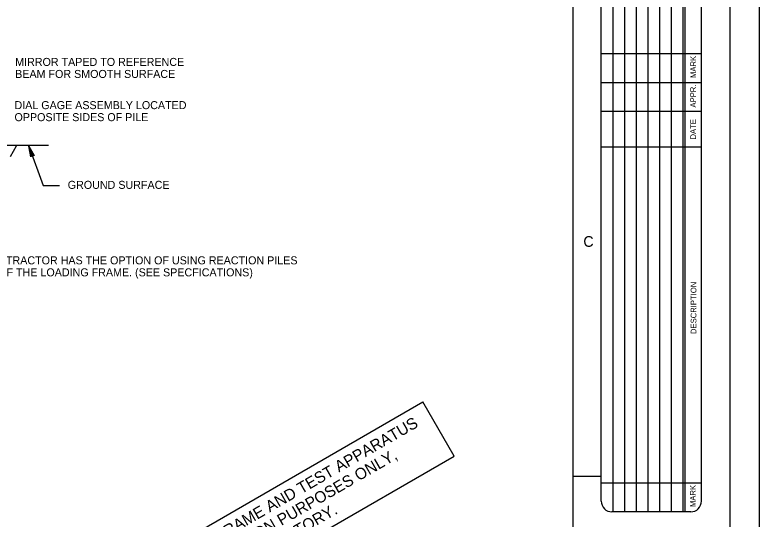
# Model space of a CAD drawing. Extents: x 22378.6 to 22422.6, y 22377.7 to 22411.7.
# Drawn here: x 22409.64 to 22422.65, y 22393.91 to 22402.72 of the extents above; entities that cross this region are included whole.
import ezdxf

# ---------------------------------------------------------------- set-up
doc = ezdxf.new("R2010")
doc.units = 0
for name, color, linetype in [('Level 1', 7, 'Continuous'), ('Level 10', 7, 'Continuous'), ('Level 2', 7, 'Continuous'), ('Level 4', 7, 'Continuous'), ('Level 7', 7, 'Continuous'), ('Level 8', 7, 'Continuous'), ('Level 9', 7, 'Continuous')]:
    doc.layers.add(name, color=color, linetype=linetype)

msp = doc.modelspace()

# ---------------------------------------------------------------- linework, layer by layer
at = {"layer": 'Level 1'}
for p, q in [((22420.089, 22409.031), (22420.089, 22394.031)), ((22420.293, 22409.031), (22420.293, 22394.031)), ((22420.497, 22409.031), (22420.497, 22394.031)), ((22420.701, 22409.031), (22420.701, 22394.031)), ((22420.905, 22409.031), (22420.905, 22394.031)), ((22421.109, 22409.031), (22421.109, 22394.031)), ((22421.313, 22409.031), (22421.313, 22394.031)), ((22421.349, 22409.031), (22421.349, 22394.031)), ((22421.637, 22401.531), (22419.885, 22401.531)), ((22409.557, 22400.242), (22409.665, 22400.43)), ((22409.881, 22400.423), (22410.128, 22399.736)), ((22409.881, 22400.423), (22409.881, 22400.423)), ((22409.898, 22400.374), (22409.898, 22400.374)), ((22410.128, 22399.736), (22410.417, 22399.736)), ((22421.45, 22394.031), (22420.073, 22394.031))]:
    msp.add_line(p, q, dxfattribs=at)
msp.add_lwpolyline([(22378.629, 22411.659), (22422.645, 22411.659), (22422.645, 22377.651), (22378.629, 22377.651)], close=True, dxfattribs=at)
for points in [[(22419.885, 22394.219), (22419.885, 22408.844)], [(22421.637, 22394.219), (22421.637, 22408.844)], [(22409.915, 22400.236), (22409.881, 22400.423), (22409.973, 22400.257), (22409.923, 22400.239), (22409.898, 22400.374), (22409.961, 22400.261), (22409.929, 22400.25), (22409.915, 22400.327), (22409.949, 22400.266), (22409.936, 22400.261), (22409.933, 22400.278)]]:
    msp.add_lwpolyline(points, dxfattribs=at)
for centre, start, end in [((22420.073, 22394.219), 180, 270), ((22421.45, 22394.219), 270, 0)]:
    msp.add_arc(centre, 0.187, start, end, dxfattribs=at)
at = {"layer": 'Level 10'}
for p, q in [((22411.269, 22392.778), (22416.767, 22395.953)), ((22417.314, 22395.006), (22416.767, 22395.953)), ((22411.816, 22391.832), (22417.314, 22395.006)), ((22419.393, 22394.655), (22419.885, 22394.655))]:
    msp.add_line(p, q, dxfattribs=at)
at = {"layer": 'Level 2'}
msp.add_line((22410.223, 22400.436), (22404.71, 22400.436), dxfattribs=at)
at = {"layer": 'Level 7'}
for p, q in [((22421.637, 22401.027), (22419.885, 22401.027)), ((22421.637, 22400.402), (22419.885, 22400.402)), ((22421.637, 22394.535), (22419.885, 22394.535))]:
    msp.add_line(p, q, dxfattribs=at)
msp.add_lwpolyline([(22421.637, 22402.035), (22419.885, 22402.035)], dxfattribs=at)
at = {"layer": 'Level 9'}
msp.add_line((22422.141, 22378.155), (22422.141, 22411.155), dxfattribs=at)
msp.add_lwpolyline([(22419.393, 22378.155), (22419.393, 22411.155)], dxfattribs=at)

# ---------------------------------------------------------------- texts
at = {"layer": 'Level 1'}
msp.add_text('C', height=0.187, dxfattribs=at).set_placement((22419.573, 22398.663))
at = {"layer": 'Level 4'}
for s, p in [('MIRROR TAPED TO REFERENCE', (22409.641, 22401.824)), ('BEAM FOR SMOOTH SURFACE', (22409.641, 22401.614)), ('DIAL GAGE ASSEMBLY LOCATED', (22409.629, 22401.069)), ('OPPOSITE SIDES OF PILE', (22409.629, 22400.859)), ('GROUND SURFACE', (22410.56, 22399.676)), ('THE CONTRACTOR HAS THE OPTION OF USING REACTION PILES', (22408.637, 22398.357)), ('IN LIEU OF THE LOADING FRAME. (SEE SPECFICATIONS)', (22408.637, 22398.147))]:
    msp.add_text(s, height=0.14, dxfattribs=at).set_placement(p)
at = {"layer": 'Level 7'}
for s, p in [('THE LOADING FRAME AND TEST APPARATUS', (22411.581, 22392.57)), ('IS FOR ILLUSTRATION PURPOSES ONLY,', (22411.733, 22392.306)), ('UNLESS NOTED MANDATORY.', (22411.885, 22392.043))]:
    msp.add_text(s, height=0.2, rotation=30.0029, dxfattribs=at).set_placement(p)
at = {"layer": 'Level 8'}
for s, p in [('MARK', (22421.543, 22401.613)), ('APPR.', (22421.541, 22401.097)), ('DATE', (22421.541, 22400.538)), ('DESCRIPTION', (22421.549, 22397.139)), ('MARK', (22421.538, 22394.116))]:
    msp.add_text(s, height=0.1, rotation=90, dxfattribs=at).set_placement(p)

doc.saveas('drawing.dxf')
